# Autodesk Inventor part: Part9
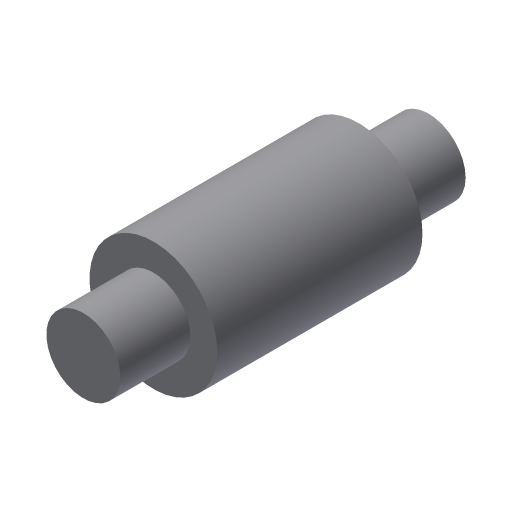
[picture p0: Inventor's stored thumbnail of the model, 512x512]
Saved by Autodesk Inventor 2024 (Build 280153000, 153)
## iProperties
Shininess: 77.0
Length Units: 11269
Angle Units: 11279
Time Units: 11290
Mass Units: 11283
Length Display Precision: 3
Angle Display Precision: 2
Created: 2002-01
Part Number: Part9
Document SubType Name: Modeling
Designer: ***
Density: 1 g/cm^3
Material: Generic
Appearance: Default
Density: 0.0
Volumn: 0.0
Area: 0.0
PropertySet Name: Model Information
Control State: 0
Master: False
Checked Out: False
Author: ***
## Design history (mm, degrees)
sketch "Sketch1"
  geometry: L1 (0.279, 23.245)-(5.19, 23.245); L2 (5.19, 23.245)-(5.19, 13.947); L3 (5.19, 13.947)-(8.761, 13.947); L4 (8.761, 13.947)-(8.761, -13.295); L5 (8.761, -13.295)-(5.19, -13.295); L6 (5.19, -13.295)-(5.19, -22.592); L7 (5.19, -22.592)-(0.279, -22.592); L8 (0.279, -22.592)-(0.279, 23.245)
  constraints: 16 end point, 5 parallel, 2 equal length, 1 collinear, 1 horizontal, 1 perpendicular
revolve "Revolution1" sketch "Sketch1" stored, may be unused: angle "d0" = 90 deg
body "Solid1"
